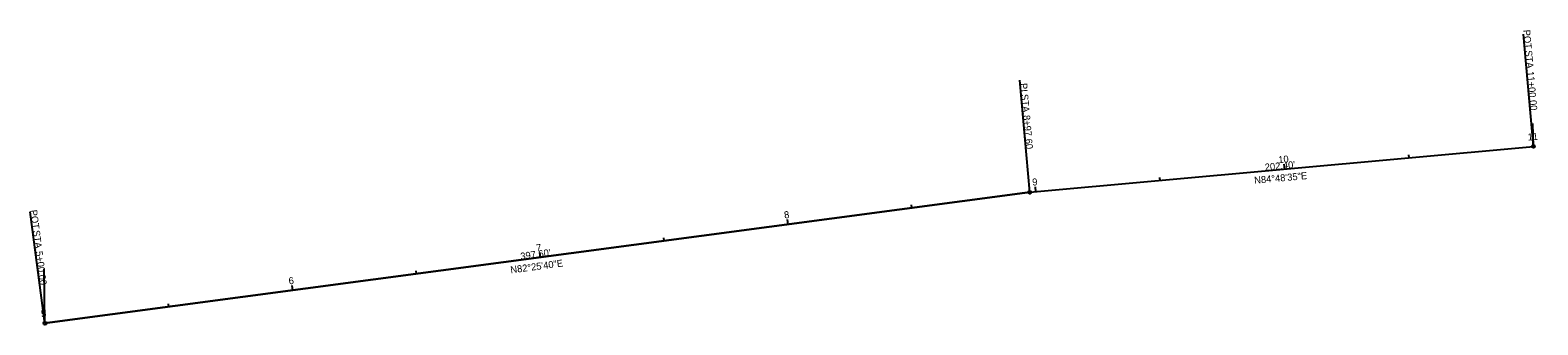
# Model space of a CAD drawing. Extents: x 226863 to 227466, y 294278 to 294395.
import ezdxf

# ---------------------------------------------------------------- set-up
doc = ezdxf.new("R2010")
doc.units = 0
for name, color, linetype in [('GE_P_Alignment', 7, 'Continuous'), ('GE_P_Alignment_100_Bearings', 7, 'Continuous'), ('GE_P_Alignment_100_Cardinal_Points', 7, 'Continuous'), ('GE_P_Alignment_100_Curve_Data', 7, 'Continuous'), ('SC_Scratch1', 7, 'Continuous'), ('SC_Scratch2', 7, 'Continuous')]:
    doc.layers.add(name, color=color, linetype=linetype)

msp = doc.modelspace()

# ---------------------------------------------------------------- linework, layer by layer
at = {"layer": 'GE_P_Alignment'}
for p, q in [((227263.03, 294330.73), (227464.6, 294349.04)), ((226868.89, 294278.34), (227263.03, 294330.73))]:
    msp.add_line(p, q, dxfattribs=at)
at = {"layer": 'GE_P_Alignment_100_Bearings'}
for p, q in [((227464.6, 294349.04), (227460.52, 294393.86)), ((227263.03, 294330.73), (227258.95, 294375.55)), ((226868.89, 294278.34), (226862.96, 294322.95))]:
    msp.add_line(p, q, dxfattribs=at)
for centre in [(227464.6, 294349.04), (227263.03, 294330.73), (226868.89, 294278.34)]:
    msp.add_circle(centre, 0.6, dxfattribs=at)
at = {"layer": 'GE_P_Alignment_100_Curve_Data'}
for p, q in [((227464.6, 294349.04), (227464.41, 294351.04)), ((227414.8, 294344.52), (227414.69, 294345.72)), ((227365.01, 294340), (227364.82, 294341.99)), ((227265.42, 294330.95), (227265.23, 294332.94)), ((227315.21, 294335.47), (227315.1, 294336.67)), ((227215.84, 294324.46), (227215.68, 294325.65)), ((227166.28, 294317.87), (227166.01, 294319.85)), ((227067.15, 294304.69), (227066.88, 294306.68)), ((227116.71, 294311.28), (227116.55, 294312.47)), ((227017.58, 294298.11), (227017.43, 294299.3)), ((226968.02, 294291.52), (226967.76, 294293.5)), ((226918.46, 294284.93), (226918.3, 294286.12)), ((226868.89, 294278.34), (226868.63, 294280.32))]:
    msp.add_line(p, q, dxfattribs=at)
at = {"layer": 'SC_Scratch1'}
for p, q in [((227464.6, 294349.04), (227464.26, 294358.15)), ((227263.03, 294330.73), (227464.6, 294349.04)), ((227263.03, 294330.73), (226868.89, 294278.34)), ((226868.89, 294278.34), (226868.59, 294300.11))]:
    msp.add_line(p, q, dxfattribs=at)

# ---------------------------------------------------------------- texts
at = {"layer": 'GE_P_Alignment_100_Bearings'}
for s, rotation, p in [('POT', 275.19038, (227460.41, 294395.54)), (' STA. ', 275.19038, (227461.07, 294388.37)), ('PI', 275.19038, (227259.12, 294374.22)), ('11+00.00', 275.19038, (227461.92, 294378.95)), (' STA. ', 275.19038, (227259.42, 294370.84)), ('8+97.60', 275.19038, (227260.28, 294361.43)), ('POT', 277.57235, (226862.93, 294323.51)), (' STA. ', 277.57235, (226863.88, 294316.37)), ('5+00.00', 277.57235, (226865.12, 294307))]:
    msp.add_text(s, height=2.8, rotation=rotation, dxfattribs=at).set_placement(p)
at = {"layer": 'GE_P_Alignment_100_Cardinal_Points'}
for s, rotation, p in [("202.40'", 5.19038, (227357.15, 294339.33)), ("397.60'", 7.57235, (227059.33, 294303.7))]:
    msp.add_text(s, height=2.8, rotation=rotation, dxfattribs=at).set_placement(p)
at = {"layer": 'GE_P_Alignment_100_Curve_Data'}
for s, rotation, p in [('11', 5.19038, (227462.34, 294351.35)), ('10', 5.19038, (227362.56, 294342.29)), ('9', 5.19038, (227264.11, 294333.34)), ('8', 7.57235, (227164.86, 294320.21)), ('7', 7.57235, (227065.65, 294307.02)), ('6', 7.57235, (226966.58, 294293.85)), ('5', 7.57235, (226867.5, 294280.68))]:
    msp.add_text(s, height=2.8, rotation=rotation, dxfattribs=at).set_placement(p)
at = {"layer": 'SC_Scratch2'}
for s, rotation, p in [('N84°48\'35"E', 5.19038, (227352.93, 294334.08)), ('N82°25\'40"E', 7.57235, (227055.33, 294298.28))]:
    msp.add_text(s, height=2.8, rotation=rotation, dxfattribs=at).set_placement(p)

doc.saveas('drawing.dxf')
